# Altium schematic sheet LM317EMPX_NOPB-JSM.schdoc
size 127 x 101 mm
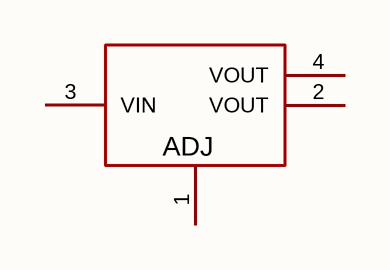
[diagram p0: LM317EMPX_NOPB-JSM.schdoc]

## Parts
U?  lm317empx/nopb-jsm  [SOT-223-3_L6.7-W3.7-P2.30-LS7.0-BR]  (value not drawn)

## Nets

Not connected (* = marked no-connect by the designer): U? 1(ADJ) 2(VOUT) 3(VIN) 4(VOUT)

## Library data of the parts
U? = lm317empx/nopb-jsm: 输出极性:正极;工作电压:37V;输出电压:1.25V~37V;输出电流:1A;电源纹波抑制比(PSRR):75dB@(120Hz);输出类型:可调;; Manufacturer: JSMSEMI(杰盛微); AddInBom: yes; ModelId: aa95d8a488c542b6aa3117a8a473808d; ModelTransform: 271.653,263.779,0,0,0,0,0,0,0; Output Configuration: 正极; Voltage - Supply: 37V; Output Current: 1A; Noise: 0.003%Vout; Output Type: 可调; Number of Outputs: 1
